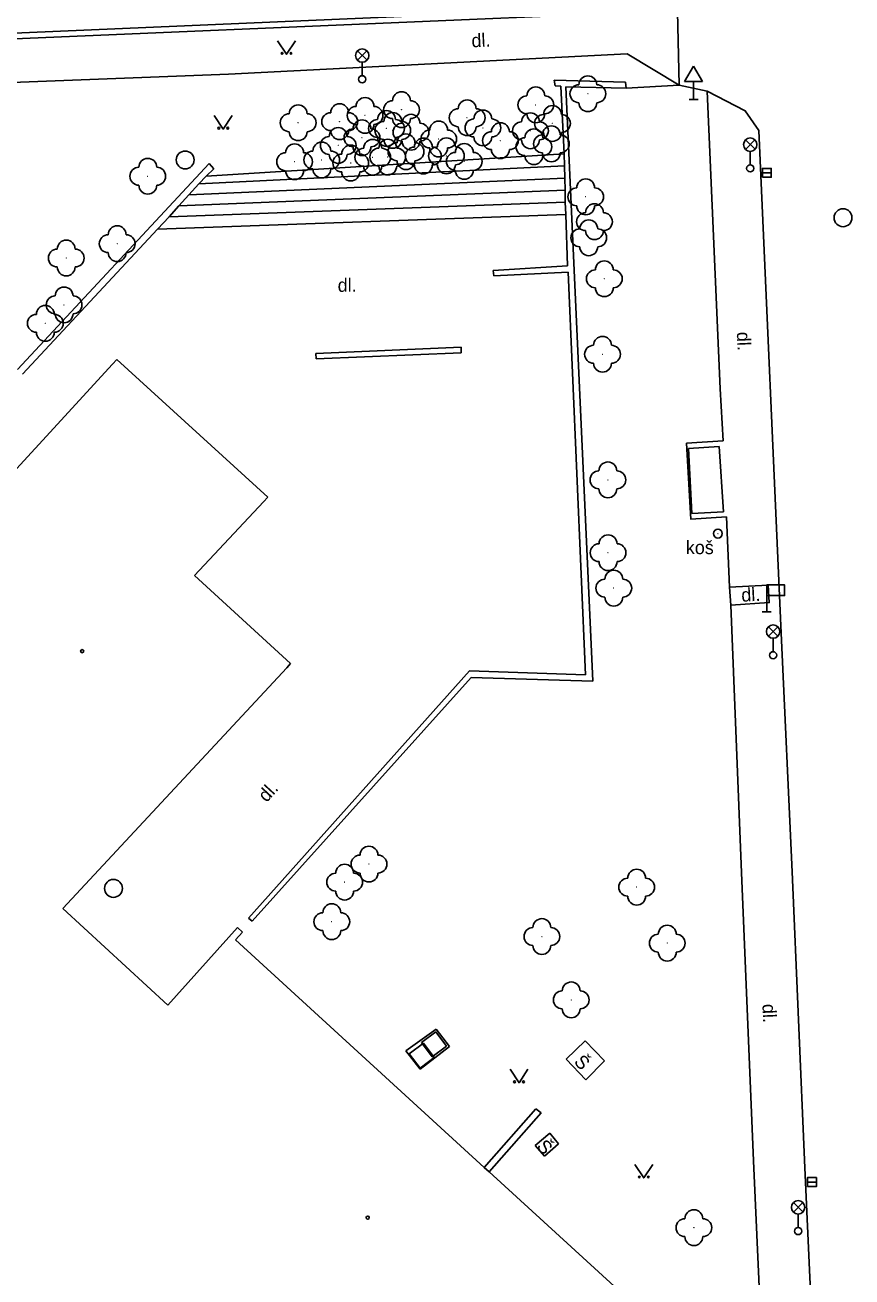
# Model space of a CAD drawing. Extents: x -737812 to -729375, y -1123000 to -1115500.
# Drawn here: x -736431 to -736384.7, y -1118447.6 to -1118377.6 of the extents above; entities that cross this region are included whole.
import ezdxf

# ---------------------------------------------------------------- set-up
doc = ezdxf.new("R2010")
doc.units = 0
for name, color, linetype in [('Doplněk polohopisu', 7, 'Continuous'), ('Doplňkové značky', 7, 'Continuous'), ('Hranice - ploty_ zdi', 7, 'Continuous'), ('Komunikace', 7, 'Continuous'), ('Pomocné popisy', 7, 'Continuous'), ('Povr_ zn_ inž_ sítí - el_', 7, 'Continuous'), ('Povr_ zn_ inž_ sítí - kan_', 7, 'Continuous'), ('Stavební objekty', 7, 'Continuous'), ('Zeleň', 7, 'Continuous'), ('Značky druhů budov', 7, 'Continuous'), ('Značky druhů pozemků', 7, 'Continuous')]:
    doc.layers.add(name, color=color, linetype=linetype)

msp = doc.modelspace()

# ---------------------------------------------------------------- linework, layer by layer
at = {"layer": 'Doplněk polohopisu'}
for points in [[(-736397.31, -1118379.22), (-736419.6, -1118380.35)], [(-736394.41, -1118380.97), (-736397.31, -1118379.22)], [(-736419.6, -1118380.35), (-736446.79, -1118381.39)], [(-736397.37, -1118381.13), (-736394.41, -1118380.97)], [(-736391.95, -1118400.85), (-736392.11, -1118397.95), (-736392.83, -1118381.3)], [(-736391.95, -1118400.85), (-736393.99, -1118400.98), (-736393.76, -1118405.22), (-736391.76, -1118405.09)], [(-736391.52, -1118410.03), (-736391.58, -1118409.02), (-736391.76, -1118405.09)], [(-736390.24, -1118441.09), (-736390.92, -1118424.97), (-736391.52, -1118410.03)], [(-736409.68, -1118434.94), (-736408, -1118433.72)], [(-736408, -1118433.72), (-736407.25, -1118434.69)], [(-736400.73, -1118435.4), (-736399.66, -1118434.37)], [(-736399.66, -1118434.37), (-736398.58, -1118435.5)], [(-736408.88, -1118435.97), (-736409.68, -1118434.94)], [(-736407.25, -1118434.69), (-736408.88, -1118435.97)], [(-736400.73, -1118435.4), (-736399.63, -1118436.55)], [(-736399.63, -1118436.55), (-736398.58, -1118435.5)], [(-736402.45, -1118440.23), (-736401.64, -1118439.53)], [(-736401.94, -1118440.82), (-736401.15, -1118440.13)], [(-736401.64, -1118439.53), (-736401.15, -1118440.13)], [(-736402.45, -1118440.23), (-736401.94, -1118440.82)], [(-736389.18, -1118464.65), (-736390.24, -1118441.09)]]:
    msp.add_lwpolyline(points, dxfattribs=at)
at = {"layer": 'Doplňkové značky'}
for p, q in [((-736393.6, -1118379.904), (-736394.1, -1118380.77)), ((-736393.6, -1118379.904), (-736393.1, -1118380.77)), ((-736394.1, -1118380.77), (-736393.1, -1118380.77)), ((-736393.6, -1118381.77), (-736393.6, -1118380.77)), ((-736393.85, -1118381.77), (-736393.35, -1118381.77)), ((-736389.51, -1118409.5), (-736389.51, -1118410.4)), ((-736389.76, -1118410.4), (-736389.26, -1118410.4))]:
    msp.add_line(p, q, dxfattribs=at)
msp.add_lwpolyline([(-736389.51, -1118409.5), (-736388.51, -1118409.5), (-736388.51, -1118408.9), (-736389.51, -1118408.9)], close=True, dxfattribs=at)
for radius in [0.25, 0.0005]:
    msp.add_circle((-736392.241, -1118406.03), radius, dxfattribs=at)
at = {"layer": 'Hranice - ploty_ zdi'}
for points in [[(-736443.31, -1118378.56), (-736396.07, -1118376.53)], [(-736396.05, -1118376.87), (-736443.42, -1118378.89)], [(-736397.4, -1118380.81), (-736401.39, -1118380.7)], [(-736401.39, -1118380.7), (-736401.33, -1118381.01)], [(-736401.33, -1118381.01), (-736401.03, -1118381.02)], [(-736400.83, -1118384.8), (-736401.03, -1118381.02)], [(-736400.74, -1118381.06), (-736399.24, -1118414.28)], [(-736400.74, -1118381.06), (-736397.37, -1118381.13)], [(-736397.4, -1118380.81), (-736397.37, -1118381.13)], [(-736400.83, -1118384.8), (-736420.86, -1118386.05)], [(-736400.75, -1118388.19), (-736400.77, -1118387.51), (-736400.78, -1118386.83), (-736400.8, -1118386.16), (-736400.81, -1118385.48), (-736400.83, -1118384.8)], [(-736420.69, -1118385.34), (-736431.41, -1118396.86)], [(-736421.26, -1118386.49), (-736400.81, -1118385.48)], [(-736420.42, -1118385.64), (-736420.69, -1118385.34)], [(-736423.57, -1118389.02), (-736422.93, -1118388.32), (-736422.38, -1118387.71), (-736421.82, -1118387.1), (-736421.26, -1118386.49), (-736420.86, -1118386.05)], [(-736421.82, -1118387.1), (-736400.8, -1118386.16)], [(-736420.86, -1118386.05), (-736420.42, -1118385.64)], [(-736422.38, -1118387.71), (-736400.78, -1118386.83)], [(-736422.93, -1118388.32), (-736400.77, -1118387.51)], [(-736400.75, -1118388.19), (-736423.57, -1118389.02)], [(-736400.64, -1118391.06), (-736400.75, -1118388.19)], [(-736423.57, -1118389.02), (-736431.12, -1118397.13)], [(-736404.81, -1118391.33), (-736400.64, -1118391.06)], [(-736404.76, -1118391.62), (-736404.81, -1118391.33)], [(-736400.62, -1118391.42), (-736404.76, -1118391.62)], [(-736399.64, -1118413.92), (-736400.62, -1118391.42)], [(-736414.72, -1118395.96), (-736406.59, -1118395.62)], [(-736414.71, -1118396.26), (-736414.72, -1118395.96)], [(-736406.59, -1118395.92), (-736414.71, -1118396.26)], [(-736406.59, -1118395.62), (-736406.59, -1118395.92)], [(-736418.48, -1118427.53), (-736406.12, -1118413.7)], [(-736406.04, -1118414.08), (-736418.28, -1118427.69)], [(-736399.64, -1118413.92), (-736406.12, -1118413.7)], [(-736399.24, -1118414.28), (-736406.04, -1118414.08)], [(-736418.28, -1118427.69), (-736418.48, -1118427.53)], [(-736402.42, -1118438.18), (-736405.3, -1118441.45)], [(-736402.13, -1118438.4), (-736405.03, -1118441.7)], [(-736402.42, -1118438.18), (-736402.13, -1118438.4)]]:
    msp.add_lwpolyline(points, dxfattribs=at)
at = {"layer": 'Komunikace'}
for points in [[(-736388.7, -1118411.59), (-736389.95, -1118383.5), (-736390.71, -1118382.4), (-736392.83, -1118381.3), (-736394.41, -1118380.97), (-736394.49, -1118376.85)], [(-736391.58, -1118409.02), (-736389.42, -1118408.92), (-736389.37, -1118409.89), (-736391.52, -1118410.03)], [(-736387.38, -1118441.48), (-736388.09, -1118424.93), (-736388.7, -1118411.59)], [(-736387.38, -1118441.48), (-736386.52, -1118460.22)]]:
    msp.add_lwpolyline(points, dxfattribs=at)
at = {"layer": 'Povr_ zn_ inž_ sítí - el_'}
for p, q in [((-736412.394, -1118379.578), (-736411.866, -1118379.05)), ((-736411.858, -1118379.575), (-736412.386, -1118379.046)), ((-736412.13, -1118379.69), (-736412.13, -1118380.44)), ((-736390.694, -1118384.558), (-736390.166, -1118384.03)), ((-736390.158, -1118384.555), (-736390.686, -1118384.026)), ((-736390.43, -1118384.67), (-736390.43, -1118385.42)), ((-736389.414, -1118411.768), (-736388.886, -1118411.24)), ((-736388.878, -1118411.765), (-736389.406, -1118411.236)), ((-736389.15, -1118411.88), (-736389.15, -1118412.63)), ((-736388.014, -1118443.948), (-736387.486, -1118443.42)), ((-736387.478, -1118443.945), (-736388.006, -1118443.416)), ((-736387.75, -1118444.06), (-736387.75, -1118444.81))]:
    msp.add_line(p, q, dxfattribs=at)
for centre, radius in [((-736412.13, -1118379.315), 0.375), ((-736412.13, -1118380.64), 0.2), ((-736390.43, -1118384.295), 0.375), ((-736390.43, -1118385.62), 0.2), ((-736389.15, -1118411.505), 0.375), ((-736389.15, -1118412.83), 0.2), ((-736387.75, -1118443.685), 0.375), ((-736387.75, -1118445.01), 0.2)]:
    msp.add_circle(centre, radius, dxfattribs=at)
at = {"layer": 'Povr_ zn_ inž_ sítí - kan_'}
for p, q in [((-736389.75, -1118385.87), (-736389.25, -1118385.87)), ((-736408.015, -1118433.881), (-736408.819, -1118434.475)), ((-736407.421, -1118434.685), (-736408.015, -1118433.881)), ((-736408.704, -1118434.509), (-736409.501, -1118435.114)), ((-736408.819, -1118434.475), (-736408.225, -1118435.279)), ((-736408.099, -1118435.306), (-736408.704, -1118434.509)), ((-736409.501, -1118435.114), (-736408.896, -1118435.911)), ((-736408.225, -1118435.279), (-736407.421, -1118434.685)), ((-736408.896, -1118435.911), (-736408.099, -1118435.306)), ((-736387.23, -1118442.27), (-736386.73, -1118442.27))]:
    msp.add_line(p, q, dxfattribs=at)
for points in [[(-736389.75, -1118386.121), (-736389.25, -1118386.121), (-736389.25, -1118385.62), (-736389.75, -1118385.62)], [(-736387.23, -1118442.521), (-736386.73, -1118442.521), (-736386.73, -1118442.02), (-736387.23, -1118442.02)]]:
    msp.add_lwpolyline(points, close=True, dxfattribs=at)
for centre in [(-736422.03, -1118385.15), (-736385.24, -1118388.38), (-736426.04, -1118425.86)]:
    msp.add_circle(centre, 0.5, dxfattribs=at)
at = {"layer": 'Stavební objekty'}
for p, q in [((-736392.17, -1118401.16), (-736393.89, -1118401.28)), ((-736393.89, -1118401.28), (-736393.69, -1118404.91)), ((-736391.92, -1118404.81), (-736392.17, -1118401.16)), ((-736393.69, -1118404.91), (-736391.92, -1118404.81))]:
    msp.add_line(p, q, dxfattribs=at)
for points in [[(-736439.29, -1118410.93), (-736426.1, -1118396.56)], [(-736425.85, -1118396.3), (-736426.1, -1118396.56)], [(-736417.4, -1118404), (-736425.85, -1118396.3)], [(-736421.5, -1118408.38), (-736417.64, -1118404.26)], [(-736417.64, -1118404.26), (-736417.4, -1118404)], [(-736416.14, -1118413.3), (-736421.5, -1118408.38)], [(-736428.87, -1118426.99), (-736416.34, -1118413.53), (-736416.14, -1118413.3)], [(-736422.99, -1118432.39), (-736428.87, -1118426.99)], [(-736419.1, -1118428.04), (-736422.99, -1118432.39)], [(-736418.82, -1118428.3), (-736419.21, -1118428.74)], [(-736418.82, -1118428.3), (-736419.1, -1118428.04)], [(-736395.86, -1118450.08), (-736405.03, -1118441.7), (-736405.3, -1118441.45), (-736419.21, -1118428.74)]]:
    msp.add_lwpolyline(points, dxfattribs=at)
at = {"layer": 'Zeleň'}
for centre in [(-736402.42, -1118382.07), (-736399.51, -1118381.45), (-736411.97, -1118382.66), (-736409.93, -1118382.34), (-736406.26, -1118382.79), (-736415.71, -1118383.07), (-736413.39, -1118383.01), (-736410.77, -1118383.39), (-736410.42, -1118383.5), (-736405.38, -1118383.36), (-736402.72, -1118383.52), (-736401.49, -1118383.11), (-736412.14, -1118383.91), (-736409.4, -1118383.6), (-736407.85, -1118383.98), (-736404.4, -1118384.07), (-736413.47, -1118384.34), (-736409.68, -1118384.69), (-736407.42, -1118384.92), (-736402.53, -1118384.41), (-736401.55, -1118384.25), (-736415.91, -1118385.25), (-736414.39, -1118385.15), (-736412.77, -1118385.32), (-736411.54, -1118385), (-736410.7, -1118384.99), (-736408.71, -1118384.93), (-736406.42, -1118385.23), (-736424.12, -1118386.06), (-736399.63, -1118387.21), (-736399.14, -1118388.6), (-736399.46, -1118389.5), (-736425.83, -1118389.83), (-736428.68, -1118390.63), (-736398.59, -1118391.79), (-736428.8, -1118393.25), (-736429.85, -1118394.28), (-736398.69, -1118396.01), (-736398.39, -1118403.03), (-736398.38, -1118407.1), (-736398.06, -1118409.08), (-736411.75, -1118424.5), (-736413.11, -1118425.51), (-736396.78, -1118425.79), (-736413.83, -1118427.72), (-736402.08, -1118428.55), (-736395.07, -1118428.92), (-736400.44, -1118432.09), (-736393.58, -1118444.82)]:
    msp.add_circle(centre, 0.0005, dxfattribs=at)
for centre, start, end in [((-736399.51, -1118380.95), 360, 179.99999), ((-736409.93, -1118381.84), 360, 179.99999), ((-736402.42, -1118381.57), 360, 179.99999), ((-736400.01, -1118381.45), 89.99999, 269.99999), ((-736399.01, -1118381.45), 270, 89.99999), ((-736415.71, -1118382.57), 360, 179.99999), ((-736413.39, -1118382.51), 360, 179.99999), ((-736411.97, -1118382.16), 360, 179.99999), ((-736410.43, -1118382.34), 89.99999, 269.99999), ((-736409.43, -1118382.34), 270, 89.99999), ((-736406.26, -1118382.29), 360, 179.99999), ((-736402.92, -1118382.07), 89.99999, 269.99999), ((-736401.49, -1118382.61), 360, 179.99999), ((-736401.92, -1118382.07), 270, 89.99999), ((-736399.51, -1118381.95), 179.99999, 359.99999), ((-736416.21, -1118383.07), 89.99999, 269.99999), ((-736415.21, -1118383.07), 270, 89.99999), ((-736413.89, -1118383.01), 89.99999, 269.99999), ((-736412.47, -1118382.66), 89.99999, 269.99999), ((-736412.89, -1118383.01), 270, 89.99999), ((-736411.47, -1118382.66), 270, 89.99999), ((-736410.77, -1118382.89), 360, 179.99999), ((-736410.42, -1118383), 360, 179.99999), ((-736409.4, -1118383.1), 360, 179.99999), ((-736406.76, -1118382.79), 89.99999, 269.99999), ((-736405.38, -1118382.86), 360, 179.99999), ((-736405.76, -1118382.79), 270, 89.99999), ((-736402.72, -1118383.02), 360, 179.99999), ((-736402.42, -1118382.57), 179.99999, 359.99999), ((-736401.99, -1118383.11), 89.99999, 269.99999), ((-736400.99, -1118383.11), 270, 89.99999), ((-736413.47, -1118383.84), 360, 179.99999), ((-736413.39, -1118383.51), 179.99999, 359.99999), ((-736412.64, -1118383.91), 89.99999, 269.99999), ((-736412.14, -1118383.41), 360, 179.99999), ((-736411.97, -1118383.16), 179.99999, 359.99999), ((-736411.27, -1118383.39), 89.99999, 269.99999), ((-736411.64, -1118383.91), 270, 89.99999), ((-736410.92, -1118383.5), 89.99999, 269.99999), ((-736409.93, -1118382.84), 179.99999, 359.99999), ((-736409.9, -1118383.6), 89.99999, 269.99999), ((-736410.27, -1118383.39), 270, 89.99999), ((-736409.92, -1118383.5), 270, 89.99999), ((-736408.9, -1118383.6), 270, 89.99999), ((-736408.35, -1118383.98), 89.99999, 269.99999), ((-736407.85, -1118383.48), 360, 179.99999), ((-736407.35, -1118383.98), 270, 89.99999), ((-736406.26, -1118383.29), 179.99999, 359.99999), ((-736405.88, -1118383.36), 89.99999, 269.99999), ((-736404.4, -1118383.57), 360, 179.99999), ((-736404.88, -1118383.36), 270, 89.99999), ((-736403.22, -1118383.52), 89.99999, 269.99999), ((-736402.53, -1118383.91), 360, 179.99999), ((-736402.22, -1118383.52), 270, 89.99999), ((-736401.55, -1118383.75), 360, 179.99999), ((-736415.71, -1118383.57), 179.99999, 359.99999), ((-736414.39, -1118384.65), 360, 179.99999), ((-736413.97, -1118384.34), 89.99999, 269.99999), ((-736412.97, -1118384.34), 270, 89.99999), ((-736411.54, -1118384.5), 360, 179.99999), ((-736410.77, -1118383.89), 179.99999, 359.99999), ((-736410.7, -1118384.49), 360, 179.99999), ((-736410.42, -1118384), 179.99999, 359.99999), ((-736410.18, -1118384.69), 89.99999, 269.99999), ((-736409.68, -1118384.19), 360, 179.99999), ((-736409.4, -1118384.1), 179.99999, 359.99999), ((-736408.71, -1118384.43), 360, 179.99999), ((-736409.18, -1118384.69), 270, 89.99999), ((-736407.42, -1118384.42), 360, 179.99999), ((-736405.38, -1118383.86), 179.99999, 359.99999), ((-736404.9, -1118384.07), 89.99999, 269.99999), ((-736403.9, -1118384.07), 270, 89.99999), ((-736403.03, -1118384.41), 89.99999, 269.99999), ((-736402.72, -1118384.02), 179.99999, 359.99999), ((-736402.05, -1118384.25), 89.99999, 269.99999), ((-736402.03, -1118384.41), 270, 89.99999), ((-736401.49, -1118383.61), 179.99999, 359.99999), ((-736401.05, -1118384.25), 270, 89.99999), ((-736416.41, -1118385.25), 89.99999, 269.99999), ((-736415.91, -1118384.75), 360, 179.99999), ((-736415.41, -1118385.25), 270, 89.99999), ((-736414.89, -1118385.15), 89.99999, 269.99999), ((-736413.47, -1118384.84), 179.99999, 359.99999), ((-736413.89, -1118385.15), 270, 89.99999), ((-736413.27, -1118385.32), 89.99999, 269.99999), ((-736412.77, -1118384.82), 360, 179.99999), ((-736412.14, -1118384.41), 179.99999, 359.99999), ((-736412.04, -1118385), 89.99999, 269.99999), ((-736412.27, -1118385.32), 270, 89.99999), ((-736411.2, -1118384.99), 89.99999, 269.99999), ((-736411.04, -1118385), 270, 89.99999), ((-736410.2, -1118384.99), 270, 89.99999), ((-736409.21, -1118384.93), 89.99999, 269.99999), ((-736407.92, -1118384.92), 89.99999, 269.99999), ((-736407.85, -1118384.48), 179.99999, 359.99999), ((-736408.21, -1118384.93), 270, 89.99999), ((-736406.92, -1118385.23), 89.99999, 269.99999), ((-736406.42, -1118384.73), 360, 179.99999), ((-736406.92, -1118384.92), 270, 89.99999), ((-736405.92, -1118385.23), 270, 89.99999), ((-736404.4, -1118384.57), 179.99999, 359.99999), ((-736402.53, -1118384.91), 179.99999, 359.99999), ((-736401.55, -1118384.75), 179.99999, 359.99999), ((-736424.62, -1118386.06), 89.99999, 269.99999), ((-736424.12, -1118385.56), 360, 179.99999), ((-736423.62, -1118386.06), 270, 89.99999), ((-736411.54, -1118385.5), 179.99999, 359.99999), ((-736410.7, -1118385.49), 179.99999, 359.99999), ((-736409.68, -1118385.19), 179.99999, 359.99999), ((-736408.71, -1118385.43), 179.99999, 359.99999), ((-736407.42, -1118385.42), 179.99999, 359.99999), ((-736415.91, -1118385.75), 179.99999, 359.99999), ((-736414.39, -1118385.65), 179.99999, 359.99999), ((-736412.77, -1118385.82), 179.99999, 359.99999), ((-736406.42, -1118385.73), 179.99999, 359.99999), ((-736399.63, -1118386.71), 360, 179.99999), ((-736424.12, -1118386.56), 179.99999, 359.99999), ((-736400.13, -1118387.21), 89.99999, 269.99999), ((-736399.13, -1118387.21), 270, 89.99999), ((-736399.63, -1118387.71), 179.99999, 359.99999), ((-736399.14, -1118388.1), 360, 179.99999), ((-736399.64, -1118388.6), 89.99999, 269.99999), ((-736398.64, -1118388.6), 270, 89.99999), ((-736425.83, -1118389.33), 360, 179.99999), ((-736399.96, -1118389.5), 89.99999, 269.99999), ((-736399.46, -1118389), 360, 179.99999), ((-736399.14, -1118389.1), 179.99999, 359.99999), ((-736398.96, -1118389.5), 270, 89.99999), ((-736428.68, -1118390.13), 360, 179.99999), ((-736426.33, -1118389.83), 89.99999, 269.99999), ((-736425.33, -1118389.83), 270, 89.99999), ((-736429.18, -1118390.63), 89.99999, 269.99999), ((-736428.18, -1118390.63), 270, 89.99999), ((-736425.83, -1118390.33), 179.99999, 359.99999), ((-736399.46, -1118390), 179.99999, 359.99999), ((-736428.68, -1118391.13), 179.99999, 359.99999), ((-736398.59, -1118391.29), 360, 179.99999), ((-736399.09, -1118391.79), 89.99999, 269.99999), ((-736398.09, -1118391.79), 270, 89.99999), ((-736428.8, -1118392.75), 360, 179.99999), ((-736398.59, -1118392.29), 179.99999, 359.99999), ((-736429.85, -1118393.78), 360, 179.99999), ((-736429.3, -1118393.25), 89.99999, 269.99999), ((-736428.3, -1118393.25), 270, 89.99999), ((-736430.35, -1118394.28), 89.99999, 269.99999), ((-736429.35, -1118394.28), 270, 89.99999), ((-736428.8, -1118393.75), 179.99999, 359.99999), ((-736429.85, -1118394.78), 179.99999, 359.99999), ((-736398.69, -1118395.51), 360, 179.99999), ((-736399.19, -1118396.01), 89.99999, 269.99999), ((-736398.19, -1118396.01), 270, 89.99999), ((-736398.69, -1118396.51), 179.99999, 359.99999), ((-736398.39, -1118402.53), 360, 179.99999), ((-736398.89, -1118403.03), 89.99999, 269.99999), ((-736397.89, -1118403.03), 270, 89.99999), ((-736398.39, -1118403.53), 179.99999, 359.99999), ((-736398.88, -1118407.1), 89.99999, 269.99999), ((-736398.38, -1118406.6), 360, 179.99999), ((-736397.88, -1118407.1), 270, 89.99999), ((-736398.38, -1118407.6), 179.99999, 359.99999), ((-736398.56, -1118409.08), 89.99999, 269.99999), ((-736398.06, -1118408.58), 360, 179.99999), ((-736397.56, -1118409.08), 270, 89.99999), ((-736398.06, -1118409.58), 179.99999, 359.99999), ((-736412.25, -1118424.5), 89.99999, 269.99999), ((-736411.75, -1118424), 360, 179.99999), ((-736411.25, -1118424.5), 270, 89.99999), ((-736413.11, -1118425.01), 360, 179.99999), ((-736396.78, -1118425.29), 360, 179.99999), ((-736413.61, -1118425.51), 89.99999, 269.99999), ((-736412.61, -1118425.51), 270, 89.99999), ((-736411.75, -1118425), 179.99999, 359.99999), ((-736397.28, -1118425.79), 89.99999, 269.99999), ((-736396.28, -1118425.79), 270, 89.99999), ((-736413.11, -1118426.01), 179.99999, 359.99999), ((-736413.83, -1118427.22), 360, 179.99999), ((-736396.78, -1118426.29), 179.99999, 359.99999), ((-736414.33, -1118427.72), 89.99999, 269.99999), ((-736413.33, -1118427.72), 270, 89.99999), ((-736402.08, -1118428.05), 360, 179.99999), ((-736413.83, -1118428.22), 179.99999, 359.99999), ((-736402.58, -1118428.55), 89.99999, 269.99999), ((-736401.58, -1118428.55), 270, 89.99999), ((-736395.07, -1118428.42), 360, 179.99999), ((-736395.57, -1118428.92), 89.99999, 269.99999), ((-736394.57, -1118428.92), 270, 89.99999), ((-736402.08, -1118429.05), 179.99999, 359.99999), ((-736395.07, -1118429.42), 179.99999, 359.99999), ((-736400.44, -1118431.59), 360, 179.99999), ((-736400.94, -1118432.09), 89.99999, 269.99999), ((-736399.94, -1118432.09), 270, 89.99999), ((-736400.44, -1118432.59), 179.99999, 359.99999), ((-736394.08, -1118444.82), 89.99999, 269.99999), ((-736393.58, -1118444.32), 360, 179.99999), ((-736393.08, -1118444.82), 270, 89.99999), ((-736393.58, -1118445.32), 179.99999, 359.99999)]:
    msp.add_arc(centre, 0.5, start, end, dxfattribs=at)
at = {"layer": 'Značky druhů budov'}
for centre in [(-736427.79, -1118412.6), (-736411.82, -1118444.26)]:
    msp.add_circle(centre, 0.0875, dxfattribs=at)
at = {"layer": 'Značky druhů pozemků'}
for points in [[(-736416.86, -1118378.49), (-736416.36, -1118379.24), (-736415.86, -1118378.49)], [(-736420.4, -1118382.67), (-736419.9, -1118383.42), (-736419.4, -1118382.67)], [(-736403.86, -1118435.97), (-736403.36, -1118436.72), (-736402.86, -1118435.97)], [(-736396.88, -1118441.29), (-736396.38, -1118442.04), (-736395.88, -1118441.29)]]:
    msp.add_lwpolyline(points, dxfattribs=at)
for centre in [(-736416.61, -1118379.19), (-736416.11, -1118379.19), (-736420.15, -1118383.37), (-736419.65, -1118383.37), (-736403.61, -1118436.67), (-736403.11, -1118436.67), (-736396.63, -1118441.99), (-736396.13, -1118441.99)]:
    msp.add_circle(centre, 0.05, dxfattribs=at)

# ---------------------------------------------------------------- texts
at = {"layer": 'Pomocné popisy'}
for s, rotation, p in [('dl.', 2.90215, (-736406, -1118378.86)), ('dl.', 272.46764, (-736391.18, -1118394.77)), ('dl.', 2.90215, (-736390.91, -1118409.84)), ('dl.', 47.43665, (-736417.48, -1118421.09)), ('dl.', 272.47665, (-736389.75, -1118432.33)), ('Š', 313.72697, (-736400.33, -1118435.59)), ('Š', 310.83349, (-736402.42, -1118440.3))]:
    msp.add_text(s, height=0.75, rotation=rotation, dxfattribs=at).set_placement(p)
for s, p in [('dl.', (-736413.5, -1118392.52)), ('koš', (-736394.03, -1118407.18))]:
    msp.add_text(s, height=0.75, dxfattribs=at).set_placement(p)

doc.saveas('drawing.dxf')
